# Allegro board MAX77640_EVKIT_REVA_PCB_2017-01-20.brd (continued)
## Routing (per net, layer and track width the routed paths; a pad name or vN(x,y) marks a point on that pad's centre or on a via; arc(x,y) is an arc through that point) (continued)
RIN: length 16
  INTERNAL3 w0.254: v1(23.34,67.21) v1(23.34,71.3)
  BOTTOM w0.254: v1(23.34,67.21) 18.62,67.21 17.34,68.49 U101.3 ; U100.27 23.96,71.3 23.95,71.3 v1(23.34,71.3)
RTSN: length 8.5
  BOTTOM w0.254: U101.32 24.39,70.49 24.69,70.79 24.73,70.79 24.74,70.8 U100.26
RXD: length 28.3
  TOP w0.254: v1(35.45,74.46) v1(20.64,74.46)
  INTERNAL3 w0.254: v1(20.65,67.82) 20.65,68.11 20.64,68.12 v1(20.64,74.46)
  BOTTOM w0.254: U101.2 17.84,68.8 18.82,67.82 v1(20.65,67.82) ; U100.43 v1(35.45,74.46)
SBB0: length 39.8
  TOP w0.152: U1.C6 48.27,41.45
  TOP w0.254: 48.27,41.45 48.44,41.45 48.59,41.61 48.95,41.61 C9.2
  TOP w0.508: 53.09,42.42 53.09,42.11 52.7,42.11 52.4,41.8 v1(51.33,41.8)
  TOP w1.27: 53.09,42.42 56.73,46.06 SBB0.1 80.49,46.08 ; J201.2 80.53,46.11
  BOTTOM w0.381: v1(49.14,41.77) 49.21,41.77 49.24,41.75 R11.2 50,41.75
  BOTTOM w0.508: v1(51.33,41.8) 50.06,41.8 50,41.75
SBB1: length 38.9
  TOP w0.152: U1.D6 48.27,41.05
  TOP w0.254: 48.27,41.05 48.97,41.05 49.08,40.94 49.13,40.94 v1(49.16,40.97)
  TOP w0.508: v1(51.44,40.89) 53.47,40.89
  TOP w1.27: 53.47,40.89 56.27,40.89 58.41,38.74 SBB1.1 83.88,38.74 84.05,38.91 85.81,38.91 ; J203.2 85.8,38.93
  BOTTOM w0.508: v1(49.16,40.97) 50.61,40.97 50.7,40.89 v1(51.44,40.89)
SBB2: length 43.1
  TOP w0.152: 48.23,40.52 48.1,40.65 U1.E6
  TOP w0.254: 49.13,40.21 48.55,40.21 48.23,40.52
  TOP w0.508: v1(52.16,40.15) 52.18,40.15 53.21,39.12
  TOP w1.27: SBB2.1 84.07,31.55 84.11,31.59 85.87,31.59 ; SBB2.1 60.78,31.55 53.21,39.12 ; SBB2.1 78.37,31.54 ; J205.2 84.26,31.44
  BOTTOM w0.508: v1(49.16,40.18) 51.38,40.18 51.42,40.15 v1(52.16,40.15)
SCL: length 130.6
  TOP w0.127: v2(47.29,42.68) 47.29,43.1 45.65,44.73
  TOP w0.152: v1(16.05,48.26) 20.29,48.26 23.55,45.01 26.87,45.01 27.15,44.73 45.65,44.73 ; v1(16.1,24.5) 15.49,24.5 15.49,24.5 J2.8
  TOP w0.254: v1(21.82,61.72) 20.56,61.72 20.53,61.69 SCL.1 18.17,61.69 18.12,61.73 v1(16.24,61.73)
  INTERNAL2 w0.152: v2(47.29,42.68) 47.29,42.59 v2(47.29,41.85)
  INTERNAL3 w0.152: v1(16.24,61.73) 16.24,61.13 16.1,60.99 16.1,48.51 ; 16.1,48.51 16.05,48.46 v1(16.05,48.26) ; 16.1,48.51 v1(16.1,24.5)
  INTERNAL3 w0.254: v1(21.82,61.72) 21.82,72.82 22.35,73.36 v1(22.35,89.94)
  BOTTOM w0.254: R107.2 32.17,89.27 R136.2 32.16,89.65 31.85,89.97 22.99,89.97 22.96,89.94 v1(22.35,89.94)
SCL1: length 60.3
  TOP w0.254: v1(30.86,76.79) v1(58,76.79)
  INTERNAL3 w0.254: J100.3 57.96,92.77 58.01,92.73 v1(58.01,82.44) v1(58.01,79.33) 58.01,78.72 58,78.72 v1(58,76.79)
  BOTTOM w0.203: R305.1 v1(58.01,82.44)
  BOTTOM w0.254: U107.9 31.33,81.9 30.61,81.18 30.61,77.75 30.93,77.43 R118.1 31.41,77.42 R155.2 v1(30.86,76.79) ; R162.1 v1(58.01,79.33)
SDA: length 126.6
  TOP w0.127: 45.18,43.71 45.44,43.71 46.65,42.49 46.65,42.48 46.76,42.36 46.76,42.36 46.87,42.25 U1.A3
  TOP w0.152: SDA.1 18.36,56.19 18.35,56.2 v1(16.97,56.2) ; 45.18,43.71 23.14,43.71 20.35,46.51 v1(16.97,46.51) ; J2.9 3.76,22.81 16.38,22.81 16.41,22.84 v1(16.97,22.84)
  TOP w0.254: SDA.1 20.67,56.19 20.72,56.24 v1(22.45,56.24)
  INTERNAL3 w0.152: v1(16.97,22.84) v1(16.97,46.51) v1(16.97,56.2)
  INTERNAL3 w0.254: v1(22.45,56.24) 22.45,72.57 22.94,73.05 22.94,88.58 23.01,88.66 v1(23.01,89.27)
  BOTTOM w0.254: R135.2 30.51,89.28 R108.2 v1(23.01,89.27)
SDA1: length 57.9
  TOP w0.254: v1(54.34,77.46) v1(33.09,77.46) v1(30.01,77.46) ; v1(54.34,83.37) 61.03,83.37 61.1,83.3 v1(61.7,83.3)
  INTERNAL3 w0.254: v1(61.7,83.3) 61.7,83.91 61.7,83.92 61.7,85.14 60.5,86.34 J100.4 ; v1(54.34,77.46) v1(54.34,83.37)
  BOTTOM w0.203: R306.1 v1(61.7,83.3)
  BOTTOM w0.254: R148.2 32.45,77.46 R100.1 v1(33.09,77.46) ; v1(30.01,77.46) 30.01,83.12 30.23,83.34 U107.10 ; R164.2 53.75,77.46 v1(54.34,77.46)
TXD: length 20.3
  TOP w0.254: v1(21.36,72.06) 36.88,72.06 36.91,72.03 v1(37.16,72.03)
  BOTTOM w0.254: v1(21.36,72.06) 20.79,71.49 U101.30 ; U100.44 36.43,71.3 v1(37.16,72.03)
UNNAMED_1_CL-SB-12B-1X_I99_2: length 3.3
  TOP w0.254: J5.1 7.5,61.64 7.4,61.54 SW2.2
UNNAMED_1_EKCAPNP_I69_2: length 23.4
  TOP w0.254: v1(46.76,43) 45.57,44.2 27,44.2 26.78,44.42 R17.1
  INTERNAL2 w0.102: 46.99,41.76 v2(47.29,41.45)
  INTERNAL2 w0.127: 46.99,42.52 46.99,41.76
  INTERNAL2 w0.254: v1(46.76,43) 46.76,42.75 46.99,42.52
  BOTTOM w0.254: v1(46.76,43) 46.68,43.08 C12.2
UNNAMED_1_EKRESSMD_I59_1: length 2.1
  TOP w0.279: DS1.1 53.14,57.28 52.89,57.54 R7.1
UNNAMED_1_EKRESSMD_I60_1: length 2
  TOP w0.279: R8.1 52.72,56.18 52.94,56.41 DS1.2
UNNAMED_1_EKRESSMD_I61_1: length 2.2
  TOP w0.305: DS1.3 53.3,54.95 R6.1
UNNAMED_1_EKRESSMD_I72_2: length 6.7
  TOP w0.254: 57.22,56.53 56.48,57.28 DS1.4 ; 57.22,56.53 R9.2 57.23,56.32 56.98,56.32 56.91,56.24 56.91,56.13 56.32,55.53 DS1.6 ; 57.22,56.53 57.03,56.53 56.9,56.41 DS1.5
UNNAMED_1_EVQ-Q2XXXX_I7_1: length 20.4
  TOP w0.254: R2.1 13.95,60.27 13.84,60.39 J5.3 13.84,64.32 11.71,66.44 Q1.3
  TOP w0.381: SW1.1 9.35,54.05 v1(11.63,54.05)
  INTERNAL3 w0.254: v1(11.63,54.05) 11.63,57.61 13.79,59.77 13.79,60.34 13.84,60.39 J5.3
UNNAMED_1_HEADER2P_I92_2: length 3.7
  TOP w0.254: R16.2 13.96,54.37 13.93,54.35 J8.2
UNNAMED_4_10103592-0001LF_I2_1: length 5.1
  BOTTOM w0.381: C155.1 7.11,77.88 7.11,77.26 7.44,76.93 FB100.1
  BOTTOM w0.457: J6.1 6.63,74.86 7.44,75.67 FB100.1
UNNAMED_4_10103592-0001LF_I2_2: length 4.9
  BOTTOM w0.254: J6.2 9.29,74.21 9.31,74.19 R123.1
UNNAMED_4_10103592-0001LF_I2_3: length 5
  BOTTOM w0.254: J6.3 9.05,73.56 9.33,73.28 R103.1
UNNAMED_4_10103592-0001LF_I2_SHIELD10: length 19.5
  BOTTOM w0.508: R142.1 7.46,70.64 R122.1 5.54,70.78 J6.7 3.78,71.13 J6.6 2.11,72.42 J6.11 J6.10 1.91,77.46 J6.9 3.78,75.98 J6.8
UNNAMED_4_CAPNP_I101_2: length 8.8
  BOTTOM w0.254: Y101.3 36.71,79.19 C153.2 34.89,79.19 34.2,78.5 U100.41
UNNAMED_4_CAPNP_I105_2: length 8.5
  BOTTOM w0.254: U100.42 34.7,74.75 35.03,75.08 37.85,75.08 38.37,75.6 C152.2 38.95,76.85 Y101.1
UNNAMED_4_EKCAPNP_I12_1: length 18.5
  TOP w0.254: v1(13.23,74.8) 14.1,75.67 v1(19.95,75.67)
  INTERNAL3 w0.254: v1(19.95,69.87) v1(19.95,75.67)
  BOTTOM w0.254: 19.95,69.74 20.05,69.63 C159.1 ; 19.95,69.74 U101.1 ; 19.95,69.74 v1(19.95,69.87) ; U101.16 13.1,73.99 12.31,74.78 C156.2 12.28,74.8 v1(13.23,74.8)
UNNAMED_4_EKCAPNP_I29_1: length 1.3
  BOTTOM w0.508: C114.1 8.8,70.71 R142.2
UNNAMED_4_EKRESSMD_I15_2: length 3.6
  BOTTOM w0.254: R123.2 11.66,74.19 12.36,73.49 U101.15
UNNAMED_4_EKRESSMD_I16_2: length 3.4
  BOTTOM w0.254: U101.14 11.75,72.99 11.43,73.3 10.84,73.3 R103.2
UNNAMED_4_EKRESSMD_I17_1: length 1.8
  BOTTOM w0.254: U101.22 17.34,76.09 R111.1
UNNAMED_4_EKRESSMD_I17_2: length 2.2
  TOP w0.254: v1(18.01,78.11) 18.01,78.67 D100.K
  BOTTOM w0.254: v1(18.01,78.11) 18.01,77.7 17.64,77.33 R111.2
UNNAMED_4_EKRESSMD_I18_1: length 1.7
  BOTTOM w0.254: U101.21 16.84,75.83 16.83,75.84 R109.1
UNNAMED_4_EKRESSMD_I18_2: length 2.2
  TOP w0.254: v1(16.31,78.11) 16.31,78.75 D101.K
  BOTTOM w0.254: R109.2 16.78,77.32 16.31,77.79 v1(16.31,78.11)
UNNAMED_4_EKRESSMD_I87_1: length 2.2
  BOTTOM w0.254: R150.1 33.95,87.99 32.93,86.97 U107.3
UNNAMED_4_EKRESSMD_I109_1: length 3.5
  BOTTOM w0.254: U100.36 31.7,75.04 31.41,75.33 R155.1
UNNAMED_4_EKRESSMD_I113_1: length 3.4
  BOTTOM w0.254: U100.37 32.2,75.03 32.45,75.28 R148.1
UNNAMED_4_EKRESSMD_I153_1: length 1.8
  BOTTOM w0.254: R135.1 31.34,87.8 31.33,87.79 U107.1
UNNAMED_4_EKRESSMD_I154_1: length 1.8
  BOTTOM w0.254: U107.2 32.13,87.75 32.16,87.78 R136.1
UNNAMED_4_EKRESSMD_I171_2: length 1.7
  BOTTOM w0.381: U107.6 35.07,83.9 35.08,83.91 R143.2
UNNAMED_4_EKRESSMD_I174_1: length 4.6
  BOTTOM w0.381: R156.2 17.31,90.18 R157.1 15.84,90.18 15.57,89.91 15.57,88.24 15.87,87.93 U104.4
UNNAMED_4_EKRESSMD_I177_1: length 1.7
  BOTTOM w0.381: U102.4 47.23,87 R159.1 45.53,87 R158.2
UNNAMED_4_EKRESSMD_I190_2: length 2.6
  BOTTOM w0.254: R152.2 32.12,81.83 32.13,81.85 U107.8
  BOTTOM w0.381: R161.2 R152.2
UNNAMED_4_LED_I7_B: length 1.8
  TOP w0.381: D102.K v1(52.22,87.25)
  BOTTOM w0.381: v1(52.22,87.25) 52.22,86.76 R110.1
UNNAMED_4_LED_I189_B: length 2.6
  TOP w0.381: D103.K 35.69,81.25 35.68,81.25 v1(35.01,81.25)
  BOTTOM w0.381: R161.1 v1(35.01,81.25)
UNNAMED_4_MAX8512_I5_FB: length 2.4
  BOTTOM w0.381: R160.2 R1.1 8.78,89.14 U103.4
UNNAMED_6_24AA02_I452_SCL: length 2.5
  BOTTOM w0.381: U108.1 51.43,79.3 51.47,79.33 R162.2
UNNAMED_6_24AA02_I452_SDA: length 2.4
  BOTTOM w0.381: R164.1 52.13,77.39 52.11,77.4 U108.3
UNNAMED_6_24AA02_I452_VCC: length 2.9
  BOTTOM w0.381: U108.4 47.44,77.37 C14.2 45.52,77.37 45.49,77.4 R163.1
UNNAMED_6_CAPNP_I21_1: length 29.5
  INTERNAL3 w0.254: v1(58.67,51.97) 58.67,48.66 58.49,48.48 v1(58.49,47.78) ; v1(69.82,52.53) 69.82,52.22 69.87,52.17 v1(69.87,44.63)
  BOTTOM w0.254: R202.2 58.92,47.78 v1(58.49,47.78) ; v1(58.67,51.97) 65.25,51.97 65.81,52.53 v1(69.82,52.53) ; U200.7 68.81,46.91 69.16,46.56 69.16,46.27 69.42,46.02 69.62,46.02 69.86,45.78 C203.1 ; C203.1 69.83,45.79 69.83,45.89 70.7,45.89 R205.1 ; C203.1 69.87,45.75 v1(69.87,44.63)
UNNAMED_6_CAPNP_I271_2: length 16
  BOTTOM w0.127: R229.1 77.16,42.82 73.2,38.86 69.69,38.86 68.47,37.64 U201.5
  BOTTOM w0.152: 70.43,38.86 70.41,38.88 R295.1
  BOTTOM w0.254: R226.2 67.37,40.27 C208.2 67.37,38.25 67.36,38.24 U201.5
UNNAMED_6_CAPNP_I277_1: length 22.8
  INTERNAL3 w0.254: v1(57.1,33.32) 58.42,34.65 v1(58.42,37.21) ; v1(69.34,33.35) v1(69.34,34.85)
  BOTTOM w0.254: R223.2 58.95,37.21 v1(58.42,37.21) ; v1(69.34,34.85) R228.1 ; R228.1 69.25,35.62 68.54,36.34 U201.7 ; R228.1 69.35,35.64 C209.1 ; v1(69.34,33.35) 61.57,33.35 61.54,33.32 v1(57.1,33.32)
UNNAMED_6_CAPNP_I277_2: length 15.2
  BOTTOM w0.127: 68.55,37 68.55,37.33 69.75,38.52 73.39,38.52 76.89,42.03 R230.1
  BOTTOM w0.152: 70.41,38.52 70.43,38.5 R296.2
  BOTTOM w0.254: 68.54,36.99 68.55,37 ; 68.54,36.99 69.2,36.99 R228.2 70.34,36.84 C209.2 ; 68.54,36.99 U201.6
UNNAMED_6_CAPNP_I289_2: length 3.2
  BOTTOM w0.254: R224.2 60.11,37.91 60.42,37.6 60.42,37.57 60.75,37.24 C248.2 60.84,37.16 61.02,36.99 U201.3
UNNAMED_6_CAPNP_I307_2: length 15.9
  BOTTOM w0.127: R242.1 78.01,35.33 77.58,34.9 77.23,34.9 73.14,30.81 70.21,30.81 68.96,29.56 67.99,29.56
  BOTTOM w0.152: 70.56,30.81 70.57,30.82 R297.1
  BOTTOM w0.254: R240.2 67.4,30.89 C214.2 67.39,30.2 67.42,30.17 U202.5 67.99,29.56
UNNAMED_6_CAPNP_I311_1: length 24.1
  INTERNAL3 w0.254: v1(58.93,29.71) v1(58.93,24.71) ; v1(70.26,24.71) v1(70.26,26.92)
  BOTTOM w0.254: v1(58.93,24.71) v1(70.26,24.71) ; C213.1 71.16,27.74 R239.1 ; C213.1 70.26,27.57 v1(70.26,26.92) ; C213.1 69.42,27.74 69.34,27.74 68.81,28.26 U202.7 ; v1(58.93,29.71) 58.89,29.67 R236.2
UNNAMED_6_CAPNP_I311_2: length 15.9
  BOTTOM w0.127: 68.79,28.91 70.31,30.43 73.27,30.43 77.34,34.5 R243.1
  BOTTOM w0.152: R298.2 70.55,30.42 70.56,30.43
  BOTTOM w0.254: 70.12,28.91 70.13,28.91 70.17,28.94 R239.2 ; 70.12,28.91 U202.6 ; 70.12,28.91 70.12,28.92 C213.2
UNNAMED_6_CAPNP_I323_2: length 3.3
  BOTTOM w0.254: R237.2 59.85,29.69 60.27,29.69 60.47,29.49 60.47,29.49 60.55,29.41 60.55,29.41 60.81,29.16 C250.2 61.56,29.16 61.81,28.91 U202.3
UNNAMED_6_CAPNP_I341_2: length 16.8
  BOTTOM w0.127: R254.1 77.19,63.57 74.74,66.01 70.11,66.01 68.46,64.36 U203.5
  BOTTOM w0.152: R299.1 69.53,65.67 69.65,65.55
  BOTTOM w0.254: R252.2 67.4,67.21 C218.2 67.4,65.34 67.34,65.28 U203.5
UNNAMED_6_CAPNP_I345_1: length 22.5
  INTERNAL3 w0.254: v1(58.85,64.8) v1(58.85,59.19)
  BOTTOM w0.254: R253.1 70.51,61.72 C219.1 ; C219.1 69.5,61.7 69.5,60.66 68.02,59.19 v1(58.85,59.19) ; C219.1 69.4,61.72 68.06,63.06 U203.7 ; R249.2 v1(58.85,64.8)
UNNAMED_6_CAPNP_I345_2: length 16.1
  BOTTOM w0.127: R255.1 77.61,62.7 74.59,65.71 70.23,65.71 68.78,64.26 68.78,63.78
  BOTTOM w0.152: 69.35,64.83 69.53,64.66 R300.2
  BOTTOM w0.254: 68.71,63.71 U203.6 ; 68.71,63.71 69.48,62.94 C219.2 70.51,62.94 R253.2 ; 68.71,63.71 68.78,63.78
UNNAMED_6_CAPNP_I357_2: length 3.4
  BOTTOM w0.254: R250.2 60.24,64.58 60.42,64.4 60.42,64.31 60.5,64.24 60.58,64.24 C251.2 60.84,63.87 61,63.71 U203.3
UNNAMED_6_CAPNP_I359_2: length 3.2
  BOTTOM w0.254: R203.2 60.23,48.45 60.75,47.93 C200.2 61.21,47.56 U200.3
UNNAMED_6_EKCAPNP_I10_1: length 3.8
  BOTTOM w0.254: R202.1 59.88,47.72 C201.1 59.89,46.8 60.81,46.8 60.92,46.91 U200.2
UNNAMED_6_EKCAPNP_I10_2: length 1.2
  BOTTOM w0.254: C201.2 58.98,45.68 R201.1
UNNAMED_6_EKCAPNP_I203_2: length 2
  BOTTOM w0.254: C223.2 65.83,73.48 65.77,73.55 U205.1
UNNAMED_6_EKCAPNP_I237_2: length 1.1
  TOP w0.381: C239.2 86.43,48.67 v1(86.54,48.56)
  BOTTOM w0.381: Q200.8 87,48.56 v1(86.54,48.56)
UNNAMED_6_EKCAPNP_I261_2: length 1.3
  TOP w0.254: C240.2 v1(86.71,40.93)
  BOTTOM w0.381: Q201.8 87.25,40.93 v1(86.71,40.93)
UNNAMED_6_EKCAPNP_I287_1: length 4
  BOTTOM w0.254: U201.2 61.09,36.34 60.83,36.08 59.9,36.08 C206.1 59.9,37.16 R223.1
UNNAMED_6_EKCAPNP_I287_2: length 1.2
  BOTTOM w0.254: R222.1 59.01,36.07 C206.2
UNNAMED_6_EKCAPNP_I298_2: length 1.5
  TOP w0.254: v1(86.56,33.5) 86.66,33.5
  TOP w0.381: 86.66,33.5 86.61,33.56 C241.2
  BOTTOM w0.254: v1(86.56,33.5) 87.14,33.5
  BOTTOM w0.381: 87.14,33.5 Q202.8
UNNAMED_6_EKCAPNP_I321_1: length 4.1
  BOTTOM w0.254: R236.1 59.79,29 C211.1 60.37,27.97 60.67,28.26 U202.2
UNNAMED_6_EKCAPNP_I321_2: length 1.1
  BOTTOM w0.254: R235.1 58.89,26.9 C211.2
UNNAMED_6_EKCAPNP_I332_2: length 1.7
  TOP w0.381: v1(86.63,61.39) 86.18,61.39 C242.2
  BOTTOM w0.381: v1(86.63,61.39) 87.19,61.39 Q203.8
UNNAMED_6_EKCAPNP_I355_1: length 4
  BOTTOM w0.254: R249.1 59.77,63.91 C216.1 59.79,62.91 60.85,62.91 61,63.06 U203.2
UNNAMED_6_EKCAPNP_I355_2: length 1.2
  BOTTOM w0.254: R248.1 58.87,61.78 C216.2
UNNAMED_6_EKRESSMD_I42_1: length 15.5
  BOTTOM w0.127: R293.1 70.02,48.68 70.03,48.68 ; 70.03,48.68 76.06,48.68 77.31,49.93 R207.1 ; 70.03,48.68 68.98,48.68 68.52,48.21 U200.5
  BOTTOM w0.254: 67.44,50.85 R206.2 ; 67.44,50.85 C204.2 ; 67.44,50.85 67.46,50.84 67.46,49.1 67.4,49.05 U200.5
UNNAMED_6_EKRESSMD_I42_2: length 12
  BOTTOM w0.127: R211.1 85.35,51.03 85.27,50.95 84.47,50.95 82.92,49.4 79.78,49.4 79.25,49.93 R207.2
  BOTTOM w0.889: R211.1 82.84,51.59 81.95,50.7 VIL_SBB0.1
UNNAMED_6_EKRESSMD_I43_1: length 14.4
  BOTTOM w0.127: 69.98,48.36 69.06,48.36 68.63,47.93 68.63,47.59 68.66,47.56 ; 69.98,48.36 76.23,48.36 77,49.14 R208.1 ; 69.98,48.36 69.98,48.36 R294.2
  BOTTOM w0.254: U200.6 68.66,47.56 68.67,47.55 68.94,47.55 69.5,46.98 C203.2 69.99,47.11 70.7,47.11 R205.2
UNNAMED_6_EKRESSMD_I99_1: length 4.2
  BOTTOM w0.254: 60.81,45.58 60.72,45.67 R201.2 ; 60.81,45.58 60.9,45.58 61.23,45.91 61.23,45.99 61.49,46.26 U200.1 ; 60.81,45.58 60.69,45.46 R204.1
UNNAMED_6_EKRESSMD_I99_2: length 46.8
  INTERNAL3 w0.254: v1(59.17,44.6) 59.17,45.21 59.21,45.24 v1(59.21,55.68)
  BOTTOM w0.254: R204.2 v1(59.17,44.6) ; v1(59.21,55.68) 75.82,55.68 75.98,55.83 88.56,55.83 89.88,54.52 92.45,54.52 92.46,54.51 J200.1
UNNAMED_6_EKRESSMD_I207_1: length 1.6
  BOTTOM w0.254: R214.1 65.77,82.56 U205.14
UNNAMED_6_EKRESSMD_I222_2: length 1.6
  BOTTOM w0.254: R283.2 64.48,80.96 U205.12
UNNAMED_6_EKRESSMD_I273_2: length 11.7
  BOTTOM w0.127: R233.1 85.34,42.76 85.25,42.68 84.49,42.68 83.36,41.55 80.35,41.55 79.08,42.83 78.76,42.83 R229.2
  BOTTOM w0.889: R233.1 84.04,43.33 83.52,42.81 VIL_SBB1.1
UNNAMED_6_EKRESSMD_I278_1: length 4.4
  BOTTOM w0.254: U201.1 62.66,35.08 62.44,34.86 60.83,34.86 60.79,34.91 R222.2 59.89,34.89 R225.1
UNNAMED_6_EKRESSMD_I278_2: length 69.1
  INTERNAL3 w0.254: J202.1 92.7,40.14 92.7,40.02 92.56,39.88 92.56,24.52 v1(92.1,24.06) ; v1(55.02,34.01) 55.02,33.4 54.89,33.27 v1(54.89,24.06)
  BOTTOM w0.254: v1(92.1,24.06) v1(54.89,24.06) ; R225.2 v1(55.02,34.01)
UNNAMED_6_EKRESSMD_I306_2: length 12.1
  BOTTOM w0.127: R245.1 85.6,36.38 85.6,35.84 85.51,35.75 84.97,35.75 84.96,35.74 84.95,35.74 83.55,34.34 80.47,34.34 79.43,35.38 R242.2
  BOTTOM w0.889: R245.1 83.27,36.41 VIL_SBB2.1
UNNAMED_6_EKRESSMD_I313_1: length 4.1
  BOTTOM w0.254: U202.1 61.32,27.61 60.55,26.84 R235.2 59.78,26.77 R238.1
UNNAMED_6_EKRESSMD_I313_2: length 39.2
  BOTTOM w0.254: J204.1 93.94,28.19 93.98,28.14 93.98,26.13 93.19,25.33 59.19,25.33 58.88,25.65 R238.2
UNNAMED_6_EKRESSMD_I340_2: length 10.6
  BOTTOM w0.127: R254.2 79.78,63.57 80.28,63.07 83.26,63.07 83.9,63.7 85.07,63.7 85.22,63.85 R258.1
  BOTTOM w0.889: VIL_LDO.1 83.79,64.74 84.14,64.4 R258.1
UNNAMED_6_EKRESSMD_I347_1: length 4.3
  BOTTOM w0.254: U203.1 61.92,61.69 59.84,61.69 R248.2 59.76,60.78 R251.1
UNNAMED_6_EKRESSMD_I347_2: length 45.9
  INTERNAL3 w0.254: v1(58.2,60.72) 58.2,57.18 v1(58.81,56.57) ; J206.1 94.03,60.86 94.04,60.85 94.04,57.18 94.03,57.18 v1(94.03,56.57)
  BOTTOM w0.254: R251.2 v1(58.2,60.72) ; v1(94.03,56.57) v1(58.81,56.57)
UNNAMED_6_EKRESSMD_I450_2: length 1.5
  BOTTOM w0.203: R305.2 63.17,82.35 U205.10
UNNAMED_6_EKRESSMD_I451_2: length 2.7
  BOTTOM w0.203: U205.11 63.82,82.51 63.08,83.25 R306.2
UNNAMED_6_HEADER2P_I444_2: length 5.3
  BOTTOM w0.254: Q201.4 89.81,43.97 90.24,44.4 90.53,44.4 90.53,44.39 R231.2 92.19,44.39 92.73,43.85 93.99,43.85 93.96,43.82 J202.2
UNNAMED_6_HEADER2P_I446_2: length 9.6
  INTERNAL3 w0.254: 93.98,31.87 93.94,31.91 J204.2
  INTERNAL3 w0.381: v1(93.92,36.66) 93.92,35.98 93.98,35.93 93.98,31.87
  BOTTOM w0.508: v1(93.92,36.66) R244.2 92.14,36.66 92.03,36.76 Q202.4
UNNAMED_6_HEADER2P_I448_2: length 4.8
  BOTTOM w0.254: J206.2 94.03,64.68 94.04,64.7 92.79,64.7 92.71,64.77 R257.2 90.35,64.77 90.3,64.72 Q203.4
UNNAMED_6_RESSMD_I28_2: length 5.4
  BOTTOM w0.254: J200.2 94.05,51.97 94.06,51.98 91.59,51.98 91.52,51.9 R210.2 90.08,51.9 89.97,51.8 Q200.4
VIO: length 162.7
  TOP w0.152: R10.2 v1(10.06,27.92)
  TOP w0.254: v1(34.79,87.72) v1(32.78,87.72) v1(30.47,87.72) ; J2.1 9.74,42.28 v1(10.08,41.94) ; R17.2 23.3,44.42 20.68,47.04 v1(10.08,47.04)
  TOP w0.381: v1(17.14,82.7) 18.95,82.7 20.17,83.92 v1(38.18,83.92) ; v1(34.79,87.72) 35.46,87.72 35.5,87.76 v1(38.18,87.76) ; v1(17.88,47.07) 18.08,47.07 18.11,47.04
  INTERNAL3 w0.152: 10.06,27.91 v1(10.06,27.92)
  INTERNAL3 w0.254: 10.06,27.91 10.06,41.66 10.08,41.68 v1(10.08,41.94) v1(10.08,47.04) ; J3.1 8.87,15.62 8.87,26.74 v1(10.06,27.92)
  INTERNAL3 w0.381: v1(38.18,83.92) v1(38.18,87.76) 38.18,92.63 J101.5 ; v1(17.88,47.07) 17.88,56.74 17.14,57.48 v1(17.14,82.7)
  BOTTOM w0.254: R14.2 34.79,88.35 v1(34.79,87.72) ; R107.1 33.04,87.98 v1(32.78,87.72) ; R108.1 30.47,88.34 v1(30.47,87.72) 30.47,87.11 30.23,86.88 U107.12 29.86,85.5 29.08,86.28 C120.2
  BOTTOM w0.381: J101.1 J101.3 J101.5 ; R143.1 37.27,83.91 37.28,83.92 v1(38.18,83.92)
  BOTTOM w0.508: J4.1 21.89,12.26 12.24,12.26 J3.1
VSYS: length 93.3
  TOP w0.152: U1.E3 46.89,40.34 ; 47.15,40.34 47.29,40.48 U1.E4 ; U1.E2 46.49,40.34
  TOP w0.254: R2.2 v1(7.12,58.13) ; 47.15,40.34 47.15,40.17
  TOP w0.508: SW2.1 2.32,64.04 2.97,63.39 2.97,61.42 6.26,58.13 v1(7.12,58.13) ; R9.1 v1(57.45,54.35) ; C30.1 v1(43.34,18.12)
  INTERNAL3 w0.508: v1(7.12,58.13) 7.12,57.4 7.1,57.38 v1(7.1,19.94)
  BOTTOM w0.508: v1(7.1,19.94) 8.76,19.94 10.87,17.83 38.27,17.83 VSYS.1
  vias: v1(41.07,18.08) v1(41.1,17.14) v1(42.27,18.11) v1(42.27,17.17) v1(43.33,17.14) v1(43.33,15.72) v1(43.33,14.1) v1(43.28,13.03) v1(44.35,13) v1(44.4,17.12) v1(44.4,15.7) v1(44.4,14.07) v1(45.47,39.85) v1(45.47,39.19) v1(46.08,39.85) v1(46.08,39.17)
VUSB: length 171.7
  TOP w0.381: v1(46.53,85.47) 45.8,86.21 20.38,86.21 v1(18.59,84.41) v1(10.14,84.41) ; v1(48.55,70.54) v1(67.61,70.54)
  INTERNAL3 w0.381: v1(67.61,70.54) 67.61,62.02 v1(66.84,61.25) ; v1(10.14,77.91) v1(10.14,84.41) ; v1(48.55,70.54) v1(48.55,82.58) v1(48.55,94.01) ; 66.84,44.6 v1(66.85,44.6)
  INTERNAL3 w0.508: v1(66.84,26.44) v1(66.84,34.57) v1(66.84,61.25)
  BOTTOM w0.254: U101.19 15.84,76.14 C108.2 10.3,76.44 9.88,76.86 FB100.2 ; U201.8 67.36,34.58 C207.1 v1(66.84,34.57) ; v1(66.84,26.44) C212.1 67.4,26.48 67.4,27.61 U202.8 ; v1(66.84,61.25) 67.39,61.25 C217.1 67.34,61.39 U203.8 ; C202.1 67.4,45.23 U200.8
  BOTTOM w0.381: U103.3 8.82,87.53 9.14,87.86 9.74,87.86 10.12,87.48 U103.1 10.13,86.68 C110.2 10.14,85.25 v1(10.14,84.41) ; v1(18.59,84.41) 18.03,84.41 C112.2 17.75,85.49 U104.1 17.86,85.6 17.86,86.47 17.59,86.74 16.84,86.74 16.49,86.39 U104.3 ; U102.3 47.24,85.49 ; 47.24,85.49 47.51,85.76 48.38,85.76 48.65,85.49 48.65,84.7 U102.1 48.54,83.26 C118.2 v1(48.55,82.58) ; 47.24,85.49 47.24,85.58 46.83,85.58 46.72,85.47 v1(46.53,85.47) ; J100.1 51.56,94.03 51.53,94.01 v1(48.55,94.01) ; R115.1 9.02,77.88 FB100.2 ; R115.1 v1(10.14,77.91) ; R115.1 C154.2 ; v1(66.85,44.6) 66.85,44.66 C202.1

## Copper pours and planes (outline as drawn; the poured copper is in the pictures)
GROUND on TOP: 1.27,11.43 1.27,95.25 96.27,95.25 96.27,11.43 ; 17 cut-outs
GROUND on BOTTOM: 1.4,94.87 1.55,10.74 95.66,10.87 95.63,96.01 3.56,96.01 ; 29 cut-outs
GROUND on INTERNAL2: 95.25,11.43 1.27,11.43 1.27,95.25 95.25,95.25 ; 2 cut-outs
INLDO on TOP: 51.94,44.83 50.67,43.56 50.67,42.55 51.69,42.55 52.7,43.56 52.7,44.83
LDO on TOP: 72.9,60.2 72.9,58.93 75.82,58.93 75.82,60.2
LDO on TOP: 49.58,44.78 49.28,44.78 48.95,44.45 48.95,43.41 49,43.36 49.3,43.36 49.71,43.76 49.71,44.65
LXA on TOP: 45.97,35.94 45.97,38.35 47.24,38.35 47.24,35.94
LXB on TOP: 48.01,35.94 48.01,38.35 49.28,38.35 49.28,35.94
SBB0 on TOP: 53.57,42.04 56.34,42.04 59.33,45.01 86.66,45.01 86.66,47.65 57.51,47.65 53.64,43.79 52.88,43 51.79,41.91 53.42,41.88
SBB1 on TOP: 53.85,41.05 53.87,40.34 56.54,37.69 86.66,37.69 86.66,39.93 86.46,40.13 58.52,40.13 57,41.66 54.46,41.66
SBB2 on TOP: 51.59,40.31 51.59,38.53 60.55,29.57 86.56,29.57 86.77,29.77 86.77,32.61 61.26,32.61 54.25,39.62 53.54,39.62 52.73,40.31
UNNAMED_6_EKCAPNP_I237_2 on BOTTOM: 87,45.09 91.77,45.06 91.77,50.85 87,50.88
UNNAMED_6_EKCAPNP_I261_2 on BOTTOM: 87.09,41.27 87.09,37.8 91.8,37.77 91.8,41.27 90.55,42.49 90.53,43.08 87.1,43.08
UNNAMED_6_EKCAPNP_I298_2 on BOTTOM: 87.12,35.92 87.11,30.45 91.69,30.45 91.72,35.92
UNNAMED_6_EKCAPNP_I332_2 on BOTTOM: 87.38,62.1 87.38,57.79 90.93,57.81 90.98,63.73 87.4,63.73
UNNAMED_6_EKRESSMD_I42_2 on BOTTOM: 88.65,51.44 86.61,51.44 86.23,51.05 84.84,51.05 84.84,52.2 85.34,52.7 88.65,52.7
UNNAMED_6_EKRESSMD_I273_2 on BOTTOM: 88.65,44.45 88.65,43.56 86.74,43.56 86.08,42.89 84.96,42.89 84.96,44.07 85.34,44.45
UNNAMED_6_EKRESSMD_I306_2 on BOTTOM: 88.77,36.32 86.87,36.32 86.5,35.96 85.21,35.95 85.22,37.21 88.77,37.21
UNNAMED_6_EKRESSMD_I340_2 on BOTTOM: 84.84,63.88 85.98,63.88 86.36,64.26 88.9,64.26 88.9,65.66 85.22,65.66 84.84,65.28
VSYS on TOP: 39.62,18.97 39.62,12.75 44.63,12.75 44.63,18.97
VSYS on TOP: 46.35,40.51 47.24,40.51 47.24,38.86 45.21,38.86 45.21,40.11 45.95,40.11
VSYS on INTERNAL3: 35.56,60.96 35.56,12.7 60.96,12.7 60.96,60.96 ; 1 cut-out

Small or netless copper shapes (teardrops, artwork), in the pictures only: 3 on TOP, 2 on INTERNAL2

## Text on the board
Ref Des/Silkscreen Top: EN_EXT | SCL | SDA | GND | nIRQ | nRST | VIO | GPIO | nEN | PWRHLD | SW2 | SW1 | RX | TX | INTERRUPT | PENDING | 3.3V_OK | LDO | 3.3V | 1.8V | VUSB | +3.3V | SCL1 | SDA1 | ENEXT | LB 01/17 | www.maximintegrated.com | 1-408-601-1000 | MAX77640 EV KIT | REVA
FAB_NOTES: NOTES: | FINISH: | TESTING: | MISCELLANEOUS: | TOOLING: | 15.  CHECK ALL THAT APPLY | 16.  VENDOR LOGO & DATE CODE REQUIRED IN INK ON BOTTOM SIDE ONLY. DATE CODE FORMAT MUST BE YYWW ONLY | 17.  FINAL ELECTRICAL TEST TO BE PERFORMED USING PROVIDED IPC-D-356A NETLIST OR ODB++ FORMAT FILE. | 18.  A TIME DOMAIN REFLECTOMETER REPORT FOR EACH IMPEDANCE CONTROLLED LAYER AND A CERTIFICATE | 24.  THIEVING: | 23.  FINISHED SURFACE CONTACTS AND FILLED VIAS TO BE FREE OF ANY PITS. SCRATCHES PROBE MARKS | 19.  FOR BLIND AND BURIED VIA INFORMATION REFER TO DRILL CHART. | 21.  ALL MICRO-VIAS LESS THAN 0.006 INCHES FHS WILL BE PLATED SHUT WITH COPPER, UNLESS OTHERWISE SPECIFIED. | 22.  FOR VIA SIZES XX.XX INCH USE NON CONDUCTIVE VIA FILL AND CAP | 13.  DRILL SIZES ARE FINISHED HOLE SIZES. ALL HOLES SHALL BE LOCATED WITHIN .005 DTP. | 14.  CHECK ALL THAT APPLY | 25.  PEMNUT | 9.  ALL TRACES FILLETED OPTION TO ENHANCE RELIABILITY AT PAD JUNCTIONS | 10.  LAYER TO LAYER REGISTRATIONS SHALL BE WITHIN .003 INCHES. | MATERIAL: | 11.  FINISHED COPPER WEIGHT/THICKNESS: | 12.  CHECK ALL THAT APPLY | 8.  IF STATED IN THE LAMINATION DIAGRAM, THE DIELECTRIC THICKNESS OF ANY | 1.  DIMENSIONS ARE IN INCHES (EXCEPT WHERE NOTED). | 3.  THE PCB SHALL BE FABRICATED TO IPC-6012, TYPE X, CLASS 2. | 4.  BOARD MATERIAL & CONSTRUCTION SHALL MEET THE REQUIREMENTS OF UL796 | 5.  OVERALL BOARD THICKNESS REFER TO LAMINATION DIAGRAM. TOLERANCE APPLIES | 6.  BOW & TWIST NOT TO EXCEED 0.0075 IN. (0.75%) PER LINEAR INCH. | 7.  PHOTO ETCH CIRCUITRY PER ENCLOSED GERBER RS274X OR ODB++ FORMAT FILE. | 2.  BOARD MATERIAL: | ( )  APPLY SILKSCREEN TO TOP SIDE USING A NON-CONDUCTIVE, WHITE EPOXY | ( )  OTHER ________________________ | (x)  APPLY SILKSCREEN TO BOTH SIDES USING A NON-CONDUCTIVE, WHITE EPOXY | (x)  GREEN SOLDERMASK OVER BARE COPPER/BARE GOLD (BOTH SIDES) WITH LIQUID PHOTO IMAGEABLE INK (LPI) | ( )  GREEN TAIYO PSR-4000 | (X)  REFER TO LAMINATION DIAGRAM FOR FINISHED COPPER WEIGHT/THICKNESS REQUIREMENTS. | ( )  FINGERS TO BE GOLD PLATED. | ( )  FINISH CONDUCTOR SURFACES: IMMERSION GOLD, 2-5 MICRO INCHES OVER | (X)  SUPPLIER MAY ADD THIEVING TO COMPENSATE FOR LOW COPPER DENSITY AREAS ON THIS DESIGN. | ( )  SUPPLIER MAY NOT ADD THIEVING TO COMPENSATE FOR LOW COPPER DENSITY AREAS ON THIS DESIGN. | ( )  NON-CONDUCTIVE EPOXY. FILL AND CAP ALL 0.XXXX INCH DRILLED VIAS. | ( )  SILVER. FILL AND CAP ALL 0.XXXX INCH DRILLED VIAS. | ( )  ELECTODEPOSITED HARD GOLD PLATE, TYPE 1 (99.7% MIN GOLD), GRADE C | (X) LEAD FREE AND RoHS COMPLIANT OR EQUIVALENT LEAD FREE PLATING | (REQUIRED UNLESS OTHERWISE SPECIFIED IN QUOTE) | THE PCB SHALL HAVE A VERIFICATION STAMP. | OF COMPLIANCE SHALL BE PROVIDED BY VENDOR AT TIME OF SHIPMENT. | ( )  PEMNUT TO BE INSTALLED BY SUPPLIER | ( )  PEMNUT NOT TO BE INSTALLED BY SUPPLIER | OR OTHER DEFORMITIES THAT COULD EFFECT THE APPERANCE AND PERFORMACE OF THE CONTACT | SURFACE. CONTACTS ARE TO BE AS FLAT AS POSSIBLE. NOT TO EXCEED +/- 0.001" OF FLATNESS. | (x)  FINISH CONDUCTOR SURFACES: IMMERSION GOLD, 3-8 MICRO INCHES OVER | ( )  FILLETED | (X)  NOT FILLETED | SO AS TO HINDER PROPER SOLDER WICKING. | (X)  ISOLA 370HR OR EQUIVALENT | ( )  NELCO-4000-13 | ( )  MEGTRON 6 | ( )  ROGERS 4350B | ( )  ROGERS 4003C | MINIMUM BARREL PLATING OF .001 IN. PLATED HOLES SHALL NOT BE ROUGH OR IRREGULAR | ( )  ISOLA-FR408HR OR EQUIVALENT | CONTROLLED IMPEDANCE LAYER IS FOR REFERENCE ONLY. FINAL ACCEPTANCE | SHALL BE DETERMINED BY THESE LAYERS HAVING A CHARACTERISTIC | IMPEDANCE OF +/-10% OHMS AS STATED IN THE LAMINATION DIAGRAM. THE | VENDOR CAN MAKE ADJUSTMENTS AS LONG AS THE STATED IMPEDANCE AND | OVERALL BOARD THICKNESS IS MAINTAINED. ANY ADJUSTMENT MADE TO TRACE | WIDTH OR SPACING MUST HAVE PRIOR WRITTEN APPROVAL FROM MAXIM. | WHERE SPACING PERMITS. | LEGEND TO LEGEND +/- 0.007 INCHES | WORKMANSHIP SHALL CONFORM TO IPC-A-600, CLASS 2, CURRENT REVISIONS. | WITH FLAMMABILITY RATING OF 94V-O. | AFTER ALL LAMINATION AND PLATING PROCESSES. IT IS TO BE MEASURED FROM | TOP PCB METAL TO BOTTOM PCB METAL UNLESS OTHERWISE SPECIFIED. | BOW & TWIST SHOULD BE MEASURED PER IPC-TM-650, METHOD 2.4.22. | DRILL LOCATION AND SIZE CONTROLLED BY EXCELLON CNC DRILL FILE. | UNLESS OTHERWISE SPECIFIED | BASED INK PER ARTWORK. | PER ARTWORK. | THE STARTING COPPER WEIGHT/THICKNESS CAN VARY AS LONG AS THE FINISHED COPPER | WEIGHT/THICKNESS IS NOT LESS THAN THE SPECIFIED VALUE. UNLESS OTHERWISE SPECIFIED. | (KNOOP HARDNESS 130-200), CLASS 1 (50-100 MICRO INCHES THICK) IN ACCORDANCE WITH MIL-G-45204C. | GENERAL SURFACING REQUIREMENTS MUST MEET ANSI/IPC-A-600(CURRENT REV) SECTION 4.0, | CLASS 3 (50-100 MICROINCHES THICK) OVER ELECTRODEPOSITED NICKEL PLATE | IN ACCORDANCE WITH ANSI/IPC-A-600D, SECTION 4.0, CLASS 3 (200-600 MICROINCHES THICK). | 118-236 MICRO INCHES MINIMUM OF ELECTROLESS NICKEL. | 100 MICRO INCHES MINIMUM OF ELECTROLESS NICKEL. | (USE CHECKED ITEMS FOR MATERIAL) | (USE CHECKED ITEMS FOR PLATING) | (USE CHECKED ITEMS FOR TOOLING) | UNLESS OTHERWISE SPECIFIED: | NOT TO SCALE | TEMPLATE REV 1.7 | TOLERANCES UNLESS OTHERWISE SPECIFIED | +/- | FRACTIONS | SEE NOTES | .XXX +/- .005 | .XX +/- .01 | DECIMALS | ANGLES | THE INFORMATION CONTAINED IN THIS DOCUMENT | IS PROPRIETARY TO MAXIM. THE INFORMATION IN | THIS DOCUMENT IS NOT TO BE SHOWN, REPRODUCED, | OR DISCLOSED TO ANYONE OUTSIDE OF MAXIM | WITHOUT PRIOR WRITTEN PERMISSION FROM MAXIM. | DRAWN BY: | CHECKED BY: CHAD OLSON | APPR. BY: | LAKSHMI BHUJ | DATE: | 1/19/2017 | SIZE | E | DRAWING NO. | SHEET 1 OF 1 | REV | A | DESCRIPTION | REVISIONS | APPROVED | DATE | TITLE: | RELEASE | MAX77640 EVALUATION BOARD | FABRICATION DWG. | XX-XXXXXX-XX
User.25: FIGURE | SIZE | 8.0 | 12.01 | 32.0 | 35.43 | 39.37 | 45.28 | 62.99 | 70.87 | 125.0 | 41.34x25.59 | 51.18x27.56 | TOLERANCE | +3.0/-6.0 | +3.0/-3.0 | PLATED | NON-PLATED | ALL UNITS ARE IN MILS | QTY | 345 | 8 | 3 | 6 | 19 | 43 | 4 | 7 | 2 | NOTES | DRILL CHART: TOP to BOTTOM
User.28: FIGURE | SIZE | 4.0 | TOLERANCE | +0.0/-4.0 | PLATED | ALL UNITS ARE IN MILS | QTY | 47 | NOTES | DRILL CHART: TOP to INTERNAL2
